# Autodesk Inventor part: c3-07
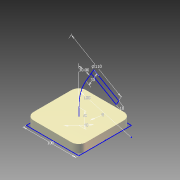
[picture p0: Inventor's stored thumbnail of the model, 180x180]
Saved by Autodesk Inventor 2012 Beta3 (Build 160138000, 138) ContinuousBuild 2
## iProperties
Created: 2010-11
Part Number: c3-07
Material: Cast Iron
Document SubType Name: Modeling
Designer: Beta-8540w
Density: 7.25 g/cm^3
Mass: 1087.5 g
Surface Area: 260 cm^2
Volume: 150 cm^3
Author: Beta-8540w
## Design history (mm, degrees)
sketch "Sketch1"
  geometry: L1 (-50, -50)-(50, -50); L2 (50, -50)-(50, 50); L3 (50, 50)-(-50, 50); L4 (-50, 50)-(-50, -50); C1 r 20 at (0, 0); C2 r 28 at (0, 0); 3 further points
  constraints: 8 end point, 3 perpendicular, 2 centre point, 2 coincident, 2 midpoint, 1 horizontal, 1 horizontal alignment, 1 parallel, 1 vertical alignment
  dimensions: "Width" = 100 distance of L1.start L1.end; "d6" = 40 diameter of C1; "d7" = 8 radial gap between concentric circles of C2 C1
extrude "Extrusion1" new body sketch "Sketch1" distance "d3" = 15; taper "d4" = 0 deg
fillet "Fillet1" dims "d5" = 14
sketch "Sketch2"
  geometry: L1 (0, 0)-(0, 30); L2 (-13.397, 80)-(-28.397, 105.981); A1 r 100 centre (-100, 30) between (0, 30) and (-13.397, 80)
  constraints: 4 end point, 2 point on circle, 2 tangent, 1 centre point, 1 vertical
  dimensions: "d8" = 30 distance of L1.start L1.end; "d9" = 100 radius of A1; "d10" = 30 distance of L2.start L2.end; "d11" = 30 deg angle of L2 L1
sketch "Sketch3"
  geometry: L1 (-13.397, 80)-(-28.397, 105.981) reference; L2 (-28.397, 105.981)-(-76.029, 78.481); L3 (-76.029, 78.481)-(-71.029, 69.821); L4 (-71.029, 69.821)-(-23.397, 97.321); L5 (-23.397, 97.321)-(-28.397, 105.981); 1 further point
  constraints: 8 end point, 2 parallel, 2 perpendicular
  dimensions: "d16" = 10 distance of L3.end L2.end; "d17" = 110 diameter of L3 L5
body "Solid1"
